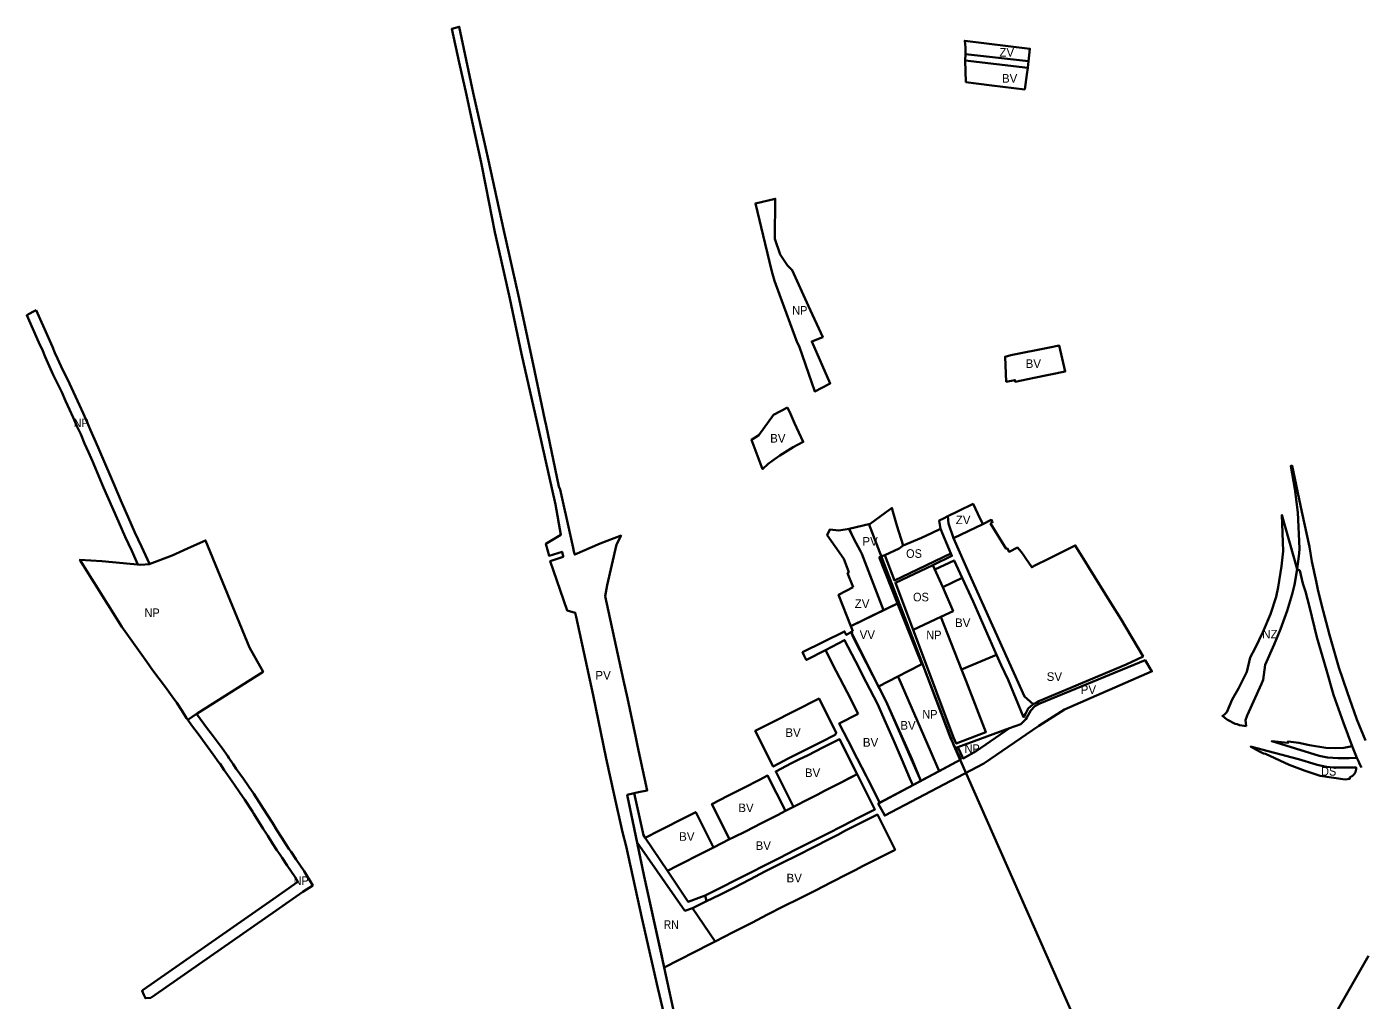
# Model space of a CAD drawing. Extents: x -650276 to -642489, y -1074311 to -1066720.
# Drawn here: x -649558 to -647696, y -1068079 to -1066720 of the extents above; entities that cross this region are included whole.
import ezdxf

# ---------------------------------------------------------------- set-up
doc = ezdxf.new("R2010")
doc.units = 0
doc.header["$LTSCALE"] = 4.8
for name, color, linetype, lineweight in [('15', 7, 'Continuous', 35), ('18', 7, 'Continuous', 35), ('24', 7, 'Continuous', 35), ('25', 7, 'Continuous', 35), ('3', 7, 'Continuous', 35), ('40', 7, 'Continuous', 35), ('45', 7, 'Continuous', 35), ('46', 7, 'Continuous', 35), ('48', 7, 'Continuous', 35), ('54', 7, 'Continuous', 35), ('7', 7, 'Continuous', 35), ('9', 7, 'Continuous', 35)]:
    doc.layers.add(name, color=color, linetype=linetype, lineweight=lineweight)
doc.layers.add('62', color=7, linetype='Continuous')

msp = doc.modelspace()

# ---------------------------------------------------------------- linework, layer by layer
at = {"layer": '15'}
for points in [[(-648662.71, -1068124.76), (-648677.61, -1068061.74), (-648700.16, -1067963.42), (-648722.09, -1067863.84), (-648727.05, -1067844.33), (-648738.7, -1067792.04), (-648749.97, -1067741.49), (-648767.84, -1067652.98), (-648791.68, -1067543.78), (-648792.97, -1067537.86), (-648804.08, -1067534.88), (-648813.94, -1067506.27), (-648827.86, -1067465.86), (-648809.65, -1067459.77), (-648809.97, -1067458.52), (-648811.21, -1067453.52), (-648811.4, -1067452.79), (-648829.54, -1067458.42), (-648834.01, -1067441.81), (-648812.91, -1067429.16), (-648820.39, -1067386.83), (-648844.16, -1067281.37), (-648845.94, -1067272.85), (-648867.82, -1067176.66), (-648884.26, -1067099.63), (-648899.1, -1067033.34), (-648905.06, -1067006.7), (-648917.76, -1066942.65), (-648924.32, -1066909.55), (-648936.7, -1066852.52), (-648944.75, -1066815.41), (-648955.15, -1066770.11), (-648965.39, -1066723.15), (-648959.88, -1066721.59), (-648954.86, -1066720.16), (-648935.19, -1066812.53), (-648918.27, -1066888.41), (-648914.11, -1066907.05), (-648893.02, -1067002.5), (-648872.31, -1067095.5), (-648851.87, -1067191.04), (-648835.29, -1067268.93), (-648833.66, -1067276.77), (-648816.06, -1067361.71), (-648813.81, -1067365.91), (-648799.58, -1067430.4), (-648796.8, -1067443.1), (-648795.88, -1067447.21), (-648794.7, -1067452.46), (-648793.71, -1067456.88), (-648757.97, -1067441.51), (-648728.95, -1067430.33), (-648735.59, -1067442.88), (-648748.53, -1067499.3), (-648751.29, -1067514.57), (-648731.06, -1067607.06), (-648725.8, -1067632.36), (-648720.1, -1067657.12), (-648708.26, -1067712.07), (-648706.08, -1067723.56), (-648702.33, -1067740.84), (-648692.53, -1067785.79), (-648704.614, -1067788.491), (-648710.961, -1067789.906), (-648720.34, -1067792), (-648696.93, -1067905.76), (-648672.31, -1068017.25), (-648668.92, -1068032.96), (-648651.89, -1068111.95)], [(-648710.961, -1067789.906), (-648720.34, -1067792), (-648706.687, -1067858.345), (-648640, -1067954)], [(-648695.27, -1067852.04), (-648697.7, -1067848.43), (-648699.621, -1067840.06), (-648699.593, -1067840.046), (-648710.96, -1067789.91)], [(-648611.61, -1067932.63), (-648620.658, -1067935.93), (-648635.249, -1067941.252), (-648664.41, -1067897.91), (-648695.27, -1067852.04)], [(-648640, -1067954), (-648629.22, -1067950.214), (-648609.91, -1067940.58), (-648611.61, -1067932.63)]]:
    msp.add_lwpolyline(points, dxfattribs=at)
for points in [[(-648161.58, -1066777.41), (-648160.51, -1066768.4), (-648248.43, -1066758.34), (-648248.77, -1066767.43)], [(-648369.01, -1067460.52), (-648361, -1067457.36), (-648341.15, -1067448.14), (-648335.38, -1067444.07), (-648344.41, -1067416.04), (-648349.67, -1067396.88), (-648351.06, -1067391.62), (-648352.16, -1067392.42), (-648353.35, -1067393.29), (-648381.48, -1067413.68), (-648410.92, -1067420.63), (-648409.61, -1067423.44), (-648404.29, -1067434.9), (-648394.92, -1067452.23), (-648393.17, -1067455.88), (-648362.585, -1067534.205), (-648343.41, -1067524.81), (-648369.01, -1067460.52)], [(-648237.81, -1067522.42), (-648204.88, -1067596.54), (-648198.39, -1067610.97), (-648193.8, -1067621), (-648189.03, -1067631.71), (-648167.48, -1067683.45), (-648164.79, -1067678.96), (-648163.11, -1067676.17), (-648160.68, -1067671.55), (-648153.98, -1067665.43), (-648166.173, -1067654.853), (-648240.51, -1067489.9), (-648265.197, -1067434.03), (-648265.197, -1067434.03), (-648272.022, -1067413.59), (-648273.008, -1067403.338), (-648279.24, -1067406.38), (-648285.08, -1067409.24), (-648283.21, -1067420.88), (-648268.67, -1067455.43), (-648267.21, -1067458.61), (-648294.04, -1067471.35), (-648291.172, -1067477.571), (-648264.34, -1067464.83), (-648253.1, -1067489.23)], [(-648359.6, -1067691.58), (-648348.55, -1067716.71), (-648337.32, -1067742.59), (-648326, -1067769), (-648321.623, -1067778.399), (-648310.511, -1067772.476), (-648323.178, -1067741.953), (-648359.213, -1067661.956), (-648405.054, -1067571.837), (-648408.002, -1067565.219), (-648414.73, -1067568.8), (-648417.19, -1067564.02), (-648475.78, -1067593.11), (-648473.34, -1067598.06), (-648470.57, -1067603.69), (-648470.47, -1067603.64), (-648443.83, -1067589.92), (-648417.12, -1067576.17), (-648402.02, -1067605.49), (-648386.91, -1067634.83), (-648371.34, -1067665.08)], [(-647988.235, -1067619.912), (-647995.04, -1067608.56), (-647997.68, -1067604.11), (-648144.83, -1067664.48), (-648151.6, -1067668.12), (-648157.2, -1067674.32), (-648161, -1067680.96), (-648162.69, -1067684), (-648164.09, -1067686.51), (-648171.21, -1067693.37), (-648187.139, -1067699.179), (-648233.264, -1067731.288), (-648251.711, -1067741.124), (-648258.96, -1067725.37), (-648262.632, -1067726.711), (-648255.016, -1067742.886), (-648319.983, -1067777.526), (-648370.113, -1067804.22), (-648360.993, -1067821.027), (-648222.872, -1067748.412), (-648146.127, -1067695.8), (-648110.36, -1067673.133), (-647988.052, -1067619.624)]]:
    msp.add_lwpolyline(points, close=True, dxfattribs=at)
at = {"layer": '18'}
msp.add_lwpolyline([(-648153.98, -1067665.43), (-648149.933, -1067663.646), (-648146.21, -1067661.3), (-648023.96, -1067610.13), (-648000.63, -1067599.14), (-648031.77, -1067546.6), (-648045.04, -1067525.15), (-648076.32, -1067474.6), (-648081.31, -1067466.54), (-648095.28, -1067444.06), (-648133.56, -1067463.2), (-648150.46, -1067471.66), (-648155.85, -1067474.35), (-648164.24, -1067462.15), (-648166.97, -1067458.18), (-648170.38, -1067453.23), (-648175.94, -1067446.89), (-648187.44, -1067452.8), (-648190.23, -1067447.83), (-648191.46, -1067448.59), (-648213.34, -1067413.46), (-648210.48, -1067411.68), (-648211.08, -1067410.6), (-648212.32, -1067408.39), (-648224.19, -1067414.14), (-648265.197, -1067434.03), (-648240.51, -1067489.9), (-648240.51, -1067489.9), (-648166.173, -1067654.853)], close=True, dxfattribs=at)
at = {"layer": '24'}
for points in [[(-647690.09, -1067716.05), (-647702.04, -1067686.86), (-647715.92, -1067648.12), (-647727.37, -1067614.33), (-647740.49, -1067568.67), (-647751.41, -1067526.58), (-647756.55, -1067505.32), (-647759.16, -1067494.01), (-647764.89, -1067466.64), (-647768.5, -1067446.04), (-647778.78, -1067397.1), (-647792.52, -1067332.74), (-647794.54, -1067333.14), (-647788.77, -1067365.03), (-647784.55, -1067398.01), (-647782.39, -1067448.34), (-647782.5, -1067455.11), (-647784.36, -1067469.6), (-647785.64, -1067477.02), (-647781.85, -1067479.19), (-647777.55, -1067496.95), (-647773.96, -1067508.48), (-647768.5, -1067529.75), (-647758.25, -1067571.79), (-647744.61, -1067617.96), (-647734.63, -1067652.57), (-647721.05, -1067691.73), (-647708.71, -1067723.99), (-647702.21, -1067740.43), (-647699.89, -1067745.24), (-647697.85, -1067749.46), (-647695.71, -1067753.9)], [(-647783.54, -1067742.11), (-647850.45, -1067724.77), (-647838.18, -1067731.62), (-647832.56, -1067734.22), (-647829.49, -1067734.58), (-647796.87, -1067750.25), (-647774.54, -1067758.68), (-647753.53, -1067765.58), (-647718.54, -1067770.6), (-647712.01, -1067769.63), (-647712.26, -1067767.28)], [(-647712.26, -1067767.28), (-647711.773, -1067767.135), (-647711.286, -1067766.968), (-647710.799, -1067766.777), (-647710.315, -1067766.562), (-647709.834, -1067766.324), (-647709.359, -1067766.062), (-647708.892, -1067765.776), (-647708.433, -1067765.466), (-647707.985, -1067765.133), (-647707.55, -1067764.777), (-647707.128, -1067764.398), (-647706.723, -1067763.999), (-647706.335, -1067763.579), (-647705.966, -1067763.14), (-647705.617, -1067762.683), (-647705.29, -1067762.21), (-647704.985, -1067761.721), (-647704.704, -1067761.22), (-647704.447, -1067760.707), (-647704.216, -1067760.184), (-647704.01, -1067759.653), (-647703.83, -1067759.117), (-647703.675, -1067758.576), (-647703.547, -1067758.033), (-647703.445, -1067757.489), (-647703.368, -1067756.946), (-647703.315, -1067756.406), (-647703.287, -1067755.87), (-647703.282, -1067755.341), (-647703.3, -1067754.818), (-647703.34, -1067754.304), (-647703.4, -1067753.8), (-647711.09, -1067753.71), (-647728.98, -1067754.07), (-647734.69, -1067753.66), (-647744.74, -1067752.93), (-647757.74, -1067749.96), (-647759.13, -1067749.54), (-647783.54, -1067742.11)]]:
    msp.add_lwpolyline(points, dxfattribs=at)
msp.add_lwpolyline([(-647754.88, -1067737.59), (-647743.12, -1067739.93), (-647728.29, -1067740.64), (-647713.15, -1067741), (-647702.21, -1067740.43), (-647708.71, -1067723.99), (-647720.45, -1067726.49), (-647732.71, -1067727.02), (-647745.41, -1067726.6), (-647768.53, -1067722.82), (-647783.13, -1067719.68), (-647798.17, -1067717.58), (-647798.5, -1067719.67), (-647821.02, -1067717.33)], close=True, dxfattribs=at)
at = {"layer": '25'}
msp.add_lwpolyline([(-647685.819, -1068016.861), (-647781.346, -1068183.485), (-647791.055, -1068200.507)], dxfattribs=at)
at = {"layer": '3'}
for points in [[(-648165.33, -1066807.74), (-648162.8, -1066786.8), (-648161.58, -1066777.41), (-648248.77, -1066767.43), (-648247.78, -1066797.53), (-648211.58, -1066802.18)], [(-648185.185, -1067178.687), (-648193.02, -1067180.66), (-648191.44, -1067215.62), (-648179.42, -1067213.37), (-648179, -1067215.71), (-648152.5, -1067210.23), (-648109.1, -1067201.21), (-648117.562, -1067165.197), (-648131.01, -1067167.84)], [(-648496.55, -1067251.53), (-648516.47, -1067261.54), (-648536.84, -1067290.29), (-648547.17, -1067296.68), (-648531.51, -1067337.57), (-648523.55, -1067330.33), (-648518.55, -1067326.3), (-648507.25, -1067318.35), (-648488.66, -1067307.11), (-648474.69, -1067299.66), (-648486.79, -1067273.26), (-648492.62, -1067260.53)], [(-648253.1, -1067489.23), (-648279.86, -1067502.11), (-648265.757, -1067535.555), (-648282.863, -1067543.596), (-648254.04, -1067616.96), (-648204.88, -1067596.54), (-648237.81, -1067522.42)], [(-648397.98, -1067678.79), (-648424.69, -1067692.54), (-648412.19, -1067716.82), (-648399.58, -1067741.31), (-648387.04, -1067765.67), (-648384.25, -1067771.07), (-648367.811, -1067802.994), (-648321.623, -1067778.399), (-648326, -1067769), (-648337.32, -1067742.59), (-648348.55, -1067716.71), (-648359.6, -1067691.58), (-648371.34, -1067665.08), (-648386.91, -1067634.83), (-648402.02, -1067605.49), (-648417.12, -1067576.17), (-648443.83, -1067589.92), (-648428.7, -1067619.24), (-648413.57, -1067648.57)], [(-648342.697, -1067626.806), (-648369.949, -1067640.851), (-648359.213, -1067661.956), (-648310.511, -1067772.476), (-648285.254, -1067759.008), (-648296.891, -1067732.172), (-648342.023, -1067628.096)], [(-648519.63, -1067691.58), (-648541.86, -1067702.86), (-648516.73, -1067752.57), (-648494.84, -1067741.06), (-648472.5, -1067729.76), (-648450.23, -1067718.32), (-648430.17, -1067708.33), (-648428.67, -1067705.52), (-648452.72, -1067657.62)], [(-648491.14, -1067748.02), (-648513.23, -1067759.38), (-648488.49, -1067808.76), (-648466.36, -1067797.5), (-648455.32, -1067791.85), (-648444.28, -1067786.19), (-648421.84, -1067774.66), (-648410.78, -1067768.98), (-648399.64, -1067763.26), (-648424.14, -1067714.34), (-648435.34, -1067720.01), (-648446.58, -1067725.71), (-648468.97, -1067736.91), (-648480.06, -1067742.47)], [(-648577.78, -1067854.07), (-648571.69, -1067851.06), (-648555.32, -1067842.99), (-648532.98, -1067831.54), (-648510.82, -1067820.19), (-648499.7, -1067814.37), (-648524.44, -1067765.11), (-648535.61, -1067770.85), (-648557.84, -1067782.26), (-648580.14, -1067793.61), (-648602.3, -1067804.83)], [(-648644.095, -1067887.6), (-648620.51, -1067875.63), (-648600.14, -1067865.29), (-648624.76, -1067816.11), (-648645.11, -1067826.48), (-648668.085, -1067838.186), (-648675.26, -1067841.84), (-648695.27, -1067852.04), (-648664.41, -1067897.91), (-648650.68, -1067890.94)]]:
    msp.add_lwpolyline(points, close=True, dxfattribs=at)
for points in [[(-648611.61, -1067932.63), (-648611.61, -1067932.63), (-648547.09, -1067899.87), (-648530.81, -1067891.61), (-648508.22, -1067880.38), (-648486.09, -1067868.98), (-648463.91, -1067857.74), (-648441.47, -1067846.37), (-648419.44, -1067835.3), (-648397.04, -1067823.85), (-648374.84, -1067812.43), (-648399.64, -1067763.26), (-648421.84, -1067774.66)], [(-648421.84, -1067774.66), (-648444.28, -1067786.19), (-648455.32, -1067791.85), (-648466.36, -1067797.5), (-648488.49, -1067808.76)], [(-648572.5, -1067983.59), (-648546.76, -1067970.44), (-648524.72, -1067958.93), (-648502.59, -1067948), (-648480.12, -1067936.55), (-648457.87, -1067925.4), (-648435.55, -1067913.84), (-648413.41, -1067902.53), (-648402.29, -1067897.02), (-648391.08, -1067891.24), (-648368.78, -1067879.75), (-648346.57, -1067868.56), (-648371.27, -1067819.47), (-648393.35, -1067830.81), (-648415.69, -1067841.98), (-648426.65, -1067847.64), (-648437.89, -1067853.4), (-648460.33, -1067864.88), (-648482.5, -1067876.22), (-648504.92, -1067887.52), (-648527.33, -1067898.74), (-648549.44, -1067910.07), (-648571.88, -1067921.71), (-648591.04, -1067931.62), (-648609.91, -1067940.58)], [(-648488.49, -1067808.76), (-648499.7, -1067814.37), (-648510.82, -1067820.19), (-648532.98, -1067831.54), (-648555.32, -1067842.99), (-648571.69, -1067851.06)], [(-648571.69, -1067851.06), (-648577.78, -1067854.07), (-648600.14, -1067865.29)], [(-648600.14, -1067865.29), (-648620.51, -1067875.63), (-648644.095, -1067887.6)], [(-648644.095, -1067887.6), (-648650.68, -1067890.94), (-648664.41, -1067897.91), (-648635.249, -1067941.252), (-648620.658, -1067935.93), (-648611.61, -1067932.63)], [(-648609.91, -1067940.58), (-648629.22, -1067950.214), (-648597.93, -1067996.72), (-648572.5, -1067983.59)]]:
    msp.add_lwpolyline(points, dxfattribs=at)
at = {"layer": '40'}
for points in [[(-648160.51, -1066768.4), (-648159.66, -1066759.8), (-648158.49, -1066750.93), (-648249.44, -1066739.8), (-648248.34, -1066749.33), (-648248.43, -1066758.34)], [(-648258.57, -1067396.29), (-648273.008, -1067403.338), (-648272.022, -1067413.59), (-648265.197, -1067434.03), (-648224.19, -1067414.14), (-648231.25, -1067399.71), (-648237.873, -1067386.174)], [(-648405.27, -1067502.27), (-648425.5, -1067512.73), (-648408.26, -1067556.58), (-648362.585, -1067534.205), (-648393.17, -1067455.88), (-648394.92, -1067452.23), (-648404.29, -1067434.9), (-648410.92, -1067420.63), (-648425, -1067423.05), (-648437.75, -1067421.99), (-648441.48, -1067429.63), (-648430.4, -1067445.51), (-648418.3, -1067462.86), (-648412.46, -1067477.42), (-648411.25, -1067481.73), (-648412.89, -1067482.55)]]:
    msp.add_lwpolyline(points, close=True, dxfattribs=at)
at = {"layer": '45'}
msp.add_lwpolyline([(-648405.41, -1067563.84), (-648408.002, -1067565.219), (-648369.949, -1067640.851), (-648342.697, -1067626.806), (-648328.54, -1067619.51), (-648309.522, -1067609.713), (-648317.43, -1067590), (-648343.41, -1067524.81), (-648408.26, -1067556.58)], close=True, dxfattribs=at)
at = {"layer": '46'}
for points in [[(-647817.59, -1067582.4), (-647808.71, -1067561.03), (-647799.39, -1067535.48), (-647792.54, -1067511.85), (-647789.39, -1067498.84), (-647785.64, -1067477.02), (-647806.8, -1067401.51), (-647804.88, -1067452.07), (-647807.17, -1067473.06), (-647811.8, -1067502.42), (-647814.89, -1067515.91), (-647822.82, -1067539.89)], [(-647822.82, -1067539.89), (-647833.51, -1067565.03), (-647844.04, -1067587.17)], [(-647835.06, -1067637.01), (-647832.8, -1067631.53), (-647829.97, -1067610.62), (-647817.59, -1067582.4)], [(-647844.04, -1067587.17), (-647850.96, -1067600.4), (-647855.65, -1067620.33), (-647867.53, -1067643.84)], [(-647856.9, -1067695.97), (-647857.51, -1067687.74), (-647855.24, -1067681.26), (-647835.06, -1067637.01)], [(-647867.53, -1067643.84), (-647876.15, -1067658.82), (-647883.78, -1067676.59), (-647886.95, -1067680.13), (-647889.94, -1067681.81), (-647884.25, -1067686.21)], [(-647884.25, -1067686.21), (-647882.82, -1067687.32), (-647871.87, -1067692.85), (-647869.32, -1067693.61), (-647865.76, -1067694.68), (-647856.9, -1067695.97)]]:
    msp.add_lwpolyline(points, dxfattribs=at)
at = {"layer": '48'}
for points in [[(-648528.01, -1067023.13), (-648518.72, -1067061.99), (-648514.86, -1067074.83), (-648507.88, -1067093.9), (-648483.31, -1067160.63), (-648480.57, -1067166.13), (-648458.73, -1067229.1), (-648449.03, -1067224.14), (-648437.02, -1067217.99), (-648462.97, -1067159.24), (-648447.66, -1067153.25), (-648467.56, -1067110.02), (-648490.23, -1067060.06), (-648496.87, -1067053.5), (-648506.78, -1067037.81), (-648514.38, -1067016.2), (-648513.842, -1066960.243), (-648541.52, -1066966.657)], [(-649545.203, -1067115.647), (-649549.7, -1067118.05), (-649558.469, -1067122.73), (-649541.537, -1067160.722), (-649536.075, -1067172.622), (-649532.831, -1067180.855), (-649529.013, -1067189.389), (-649521.663, -1067206.124), (-649514.869, -1067218.957), (-649509.44, -1067230.141), (-649504.224, -1067242.225), (-649498.572, -1067254.427), (-649493.526, -1067265.611), (-649487.812, -1067278.312), (-649482.963, -1067288.934), (-649477.677, -1067301.655), (-649472.327, -1067313.644), (-649466.703, -1067326.24), (-649451.059, -1067363.074), (-649439.265, -1067390.397), (-649430.531, -1067410.689), (-649425.804, -1067421.21), (-649421.071, -1067431.944), (-649411.913, -1067451.746), (-649403.34, -1067470.579), (-649399.39, -1067470.93), (-649387.4, -1067469.98), (-649387.17, -1067469.894), (-649398.28, -1067445.49), (-649407.4, -1067425.77), (-649412.1, -1067415.11), (-649416.8, -1067404.65), (-649425.49, -1067384.46), (-649437.27, -1067357.17), (-649452.95, -1067320.25), (-649458.63, -1067307.53), (-649463.9, -1067295.72), (-649469.21, -1067282.94), (-649474.15, -1067272.12), (-649479.85, -1067259.45), (-649484.93, -1067248.19), (-649490.53, -1067236.1), (-649495.8, -1067223.89), (-649501.49, -1067212.17), (-649508.15, -1067199.59), (-649515.3, -1067183.31), (-649519, -1067175.04), (-649522.27, -1067166.74), (-649527.87, -1067154.54)], [(-649333.74, -1067687.4), (-649335.26, -1067685.21), (-649341.81, -1067674.33), (-649349.12, -1067663.84), (-649355.46, -1067654.85), (-649364.69, -1067641.98), (-649382.53, -1067618.33), (-649391.04, -1067606.27), (-649393.23, -1067603.28), (-649425.69, -1067557.7), (-649484.28, -1067463.88), (-649453.39, -1067466.13), (-649399.39, -1067470.93), (-649387.4, -1067469.98), (-649355.44, -1067457.94), (-649329.068, -1067446.175), (-649308.75, -1067437.11), (-649247.518, -1067586.255), (-649228.52, -1067620.294), (-649320.47, -1067678.44)], [(-648342.023, -1067628.096), (-648296.891, -1067732.172), (-648285.254, -1067759.008), (-648255.016, -1067742.886), (-648265.614, -1067720.378), (-648269.27, -1067712.6), (-648308.43, -1067609.15), (-648328.54, -1067619.51), (-648342.697, -1067626.806)], [(-649321.3, -1067679), (-649333.74, -1067687.4), (-649328.34, -1067694.79), (-649317.99, -1067708.85), (-649312.91, -1067715.45), (-649298.02, -1067735.58), (-649290.15, -1067746.92), (-649288.63, -1067748.97), (-649282.85, -1067757.79), (-649278.14, -1067764.31), (-649268.46, -1067777.97), (-649261.48, -1067788.47), (-649253.98, -1067799.2), (-649243.37, -1067815.17), (-649241.28, -1067818.7), (-649228.27, -1067839.26), (-649222.11, -1067849.12), (-649215.32, -1067859.99), (-649209.39, -1067869.34), (-649204.87, -1067875.85), (-649202.02, -1067880.07), (-649194.77, -1067890.67), (-649184, -1067906.88), (-649179.96, -1067913.35), (-649219.088, -1067940.964), (-649395.729, -1068064.23), (-649397.466, -1068065.442), (-649394.83, -1068071.05), (-649392.88, -1068075.9), (-649385.41, -1068075.32), (-649379.295, -1068071.053), (-649210.54, -1067953.29), (-649172.99, -1067927.41), (-649159.179, -1067918.309), (-649171.389, -1067898.756), (-649182.332, -1067882.285), (-649189.614, -1067871.638), (-649192.493, -1067867.375), (-649196.89, -1067861.042), (-649202.625, -1067852), (-649209.388, -1067841.173), (-649215.571, -1067831.276), (-649228.486, -1067810.867), (-649230.661, -1067807.193), (-649241.584, -1067790.752), (-649249.085, -1067780.02), (-649256.092, -1067769.48), (-649265.941, -1067755.582), (-649270.491, -1067749.283), (-649276.322, -1067740.385), (-649277.961, -1067738.175), (-649285.826, -1067726.842), (-649300.936, -1067706.414), (-649306.005, -1067699.828), (-649316.244, -1067685.919)], [(-648258.96, -1067725.37), (-648251.711, -1067741.124), (-648233.264, -1067731.288), (-648187.139, -1067699.179)]]:
    msp.add_lwpolyline(points, close=True, dxfattribs=at)
for points in [[(-648265.08, -1067712.06), (-648261.25, -1067720.39), (-648235.78, -1067710.79), (-648219.86, -1067704.42), (-648247.53, -1067633.53), (-648254.04, -1067616.96), (-648282.863, -1067543.596), (-648321.36, -1067561.69)], [(-648321.361, -1067561.69), (-648311.95, -1067586.45), (-648265.08, -1067712.06)]]:
    msp.add_lwpolyline(points, dxfattribs=at)
at = {"layer": '54'}
msp.add_lwpolyline([(-648383.36, -1067413.938), (-648264.607, -1067722.965), (-648014.937, -1068288.491)], dxfattribs=at)
at = {"layer": '7'}
msp.add_lwpolyline([(-648640, -1067954), (-648706.687, -1067858.345), (-648696.93, -1067905.76), (-648668.92, -1068032.96), (-648605.323, -1068000.463), (-648597.93, -1067996.72), (-648629.22, -1067950.214)], close=True, dxfattribs=at)
at = {"layer": '9'}
for points in [[(-648268.67, -1067455.43), (-648283.21, -1067420.88), (-648295.66, -1067426.76), (-648309.57, -1067433.34), (-648335.38, -1067444.07), (-648341.15, -1067448.14), (-648361, -1067457.36), (-648347.51, -1067492.87), (-648326.09, -1067482.7)], [(-648334.09, -1067528.2), (-648321.36, -1067561.69), (-648282.863, -1067543.596), (-648265.757, -1067535.555), (-648279.86, -1067502.11), (-648294.04, -1067471.35), (-648346.27, -1067496.14)]]:
    msp.add_lwpolyline(points, close=True, dxfattribs=at)

# ---------------------------------------------------------------- texts
at = {"layer": '62'}
for s, p in [('ZV', (-648201.026, -1066761.906)), ('BV', (-648197.475, -1066798.284)), ('BV', (-648164.386, -1067196.331)), ('BV', (-648520.956, -1067300.498)), ('ZV', (-648261.918, -1067414.307)), ('PV', (-648392.213, -1067444.317)), ('ZV', (-648402.918, -1067531.307)), ('VV', (-648396.075, -1067574.614)), ('BV', (-648262.942, -1067557.923)), ('NZ', (-647834.293, -1067573.797)), ('PV', (-648764.767, -1067631.209)), ('SV', (-648135.028, -1067633.035)), ('PV', (-648087.517, -1067651.275)), ('BV', (-648339.301, -1067701.063)), ('BV', (-648499.724, -1067711.153)), ('BV', (-648391.551, -1067724.775)), ('BV', (-648472.48, -1067767.243)), ('BV', (-648565.429, -1067816.121)), ('BV', (-648647.961, -1067856.185)), ('BV', (-648541.281, -1067868.87)), ('BV', (-648498.112, -1067914.191))]:
    msp.add_text(s, height=12, dxfattribs=at).set_placement(p)
for s, width, p in [('NP', 0.95, (-648490.15, -1067121.972)), ('NP', 0.95, (-649492.985, -1067278.967)), ('OS', 0.95, (-648331.213, -1067461.317)), ('OS', 0.95, (-648321.549, -1067522.064)), ('NP', 0.95, (-649393.985, -1067543.967)), ('NP', 0.95, (-648303.019, -1067574.94)), ('NP', 0.95, (-648308.631, -1067685.579)), ('NP', 0.95, (-648249.631, -1067733.579)), ('DS', 0.95, (-647752.118, -1067765.225)), ('NP', 0.95, (-649185.985, -1067917.967)), ('RN', 0.9, (-648669.473, -1067979.058))]:
    msp.add_text(s, height=12, dxfattribs=dict(at, width=width)).set_placement(p)

doc.saveas('drawing.dxf')
